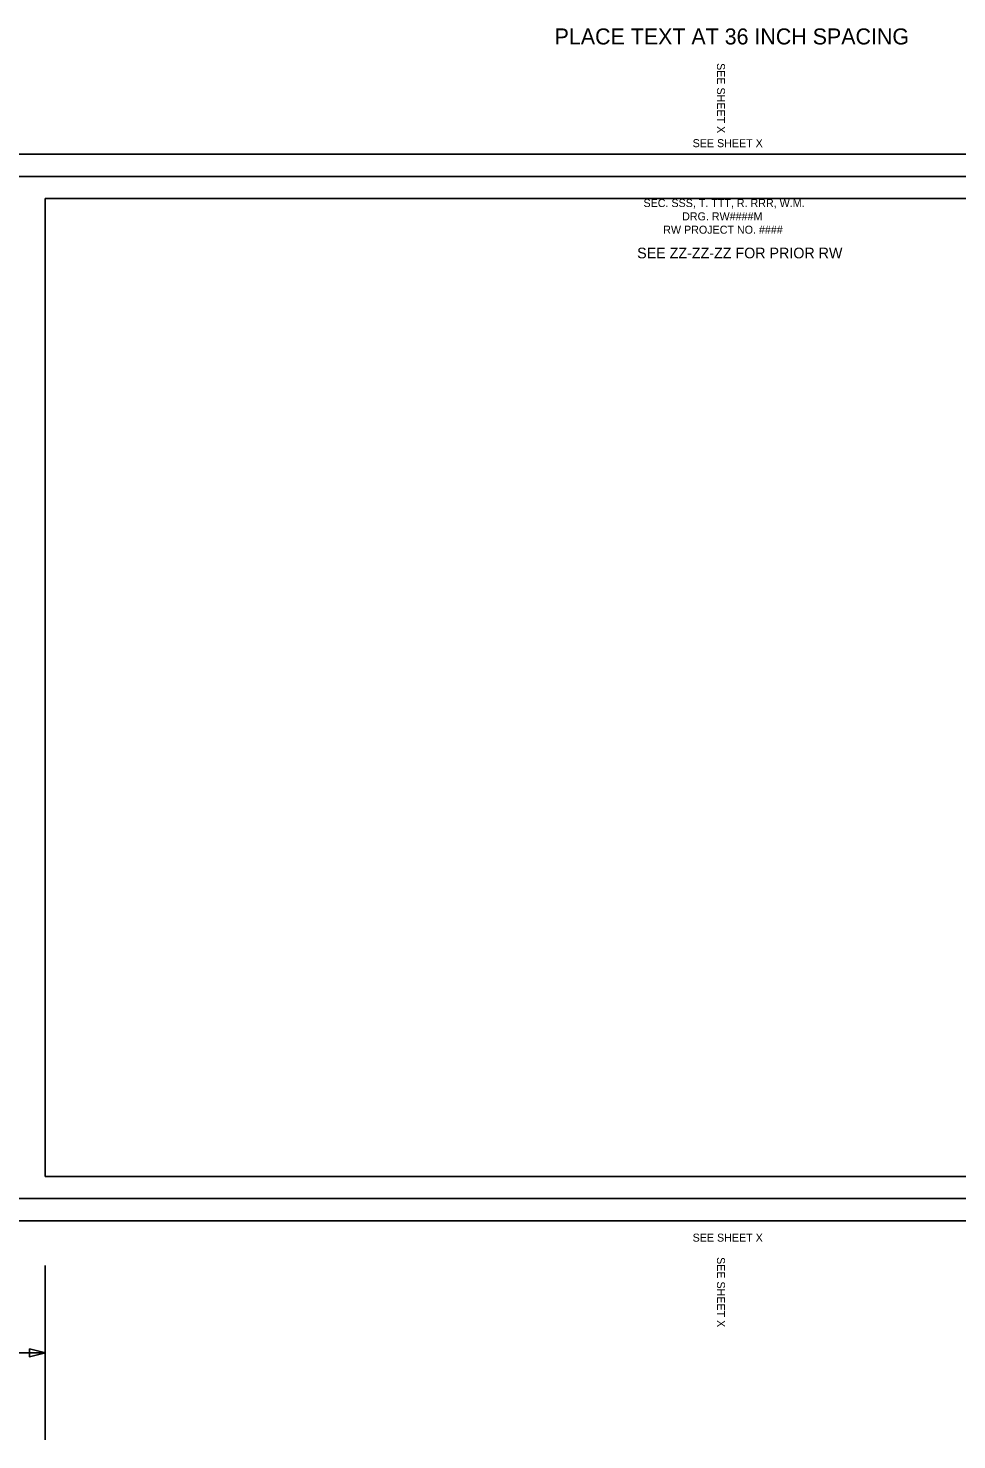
# Model space of a CAD drawing. Extents: x -1.2 to 17.3, y -1 to 2.5.
# Drawn here: x 2.01 to 3.75, y -0.41 to 2.236 of the extents above; entities that cross this region are included whole.
import ezdxf

# ---------------------------------------------------------------- set-up
doc = ezdxf.new("R2010")
doc.units = 0
for name, color, linetype in [('#plot_shape', 7, 'Continuous'), ('P_ODOT_PLAN_Border', 7, 'Continuous'), ('P_ODOT_PLAN_General', 7, 'Continuous')]:
    doc.layers.add(name, color=color, linetype=linetype)

msp = doc.modelspace()

# ---------------------------------------------------------------- linework, layer by layer
at = {"layer": '#plot_shape'}
msp.add_lwpolyline([(0, 0), (16.6667, 0), (16.6667, 2), (0, 2)], close=True, dxfattribs=at)
msp.add_lwpolyline([(0, 0), (16.6667, 0), (16.6667, 2), (0, 2)], close=True, dxfattribs=at)
at = {"layer": 'P_ODOT_PLAN_Border'}
for points in [[(0.0417, 0.0417), (16.625, 0.0417), (16.625, 1.9583), (0.0417, 1.9583)], [(0.0417, 0.0417), (16.625, 0.0417), (16.625, 1.9583), (0.0417, 1.9583)], [(2.0417, 0.0833), (15.0833, 0.0833), (15.0833, 1.9167), (2.0417, 1.9167)], [(2.0417, 0.0833), (15.0833, 0.0833), (15.0833, 1.9167), (2.0417, 1.9167)]]:
    msp.add_lwpolyline(points, close=True, dxfattribs=at)
at = {"layer": 'P_ODOT_PLAN_General'}
for p, q in [((2.0417, -0.0839), (2.0417, -0.4104)), ((2.0417, -0.0839), (2.0417, -0.4104)), ((2.0419, -0.2471), (1.275, -0.2471)), ((2.0419, -0.2471), (1.275, -0.2471))]:
    msp.add_line(p, q, dxfattribs=at)
msp.add_lwpolyline([(2.0119, -0.2396), (2.0419, -0.2471), (2.0119, -0.2546)], close=True, dxfattribs=at)
msp.add_lwpolyline([(2.0119, -0.2396), (2.0419, -0.2471), (2.0119, -0.2546)], close=True, dxfattribs=at)

# ---------------------------------------------------------------- texts
for s, height, p in [('PLACE TEXT AT 36 INCH SPACING', 0.03, (2.9964, 2.2056)), ('PLACE TEXT AT 36 INCH SPACING', 0.03, (2.9964, 2.2056)), ('SEE SHEET X', 0.015, (3.2551, 2.013)), ('SEE SHEET X', 0.015, (3.2551, 2.013)), ('SEC. SSS, T. TTT, R. RRR, W.M.', 0.015, (3.163, 1.9008)), ('SEC. SSS, T. TTT, R. RRR, W.M.', 0.015, (3.163, 1.9008)), ('DRG. RW####M', 0.015, (3.2354, 1.8758)), ('DRG. RW####M', 0.015, (3.2354, 1.8758)), ('RW PROJECT NO. ####', 0.015, (3.2, 1.8508)), ('RW PROJECT NO. ####', 0.015, (3.2, 1.8508)), ('SEE ZZ-ZZ-ZZ FOR PRIOR RW', 0.02, (3.1511, 1.8046)), ('SEE ZZ-ZZ-ZZ FOR PRIOR RW', 0.02, (3.1511, 1.8046)), ('SEE SHEET X', 0.015, (3.2551, -0.0389)), ('SEE SHEET X', 0.015, (3.2551, -0.0389))]:
    msp.add_text(s, height=height, dxfattribs=at).set_placement(p)
for p in [(3.3008, 2.1707), (3.3008, 2.1707), (3.3008, -0.0678), (3.3008, -0.0678)]:
    msp.add_text('SEE SHEET X', height=0.015, rotation=270, dxfattribs=at).set_placement(p)

doc.saveas('drawing.dxf')
